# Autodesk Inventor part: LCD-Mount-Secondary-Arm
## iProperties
Company: Autodesk, Inc.
Shininess: 64.0
Length Units: 11269
Angle Units: 11279
Time Units: 11290
Mass Units: 11283
Length Display Precision: 3
Angle Display Precision: 2
Compacted: True
Part Number: LCD-Mount-Secondary-Arm
Document SubType Name: Modeling
Created: 2003-12
Catalog Web Link: www.autodesk.com
Vendor: Autodesk, Inc.
Designer: Administrator
Manufacturer: Standard
Standards Organization: Custom
Density: 1 g/cm^3
Density: 0.0
Volumn: 0.0
Area: 0.0
PropertySet Name: Model Information
Control State: 0
Master: False
Checked Out: False
Author: Administrator
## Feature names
1. Extrusion1
2. Extrusion2
3. Extrusion3
4. Hole1
5. Fillet1
6. Hole2
